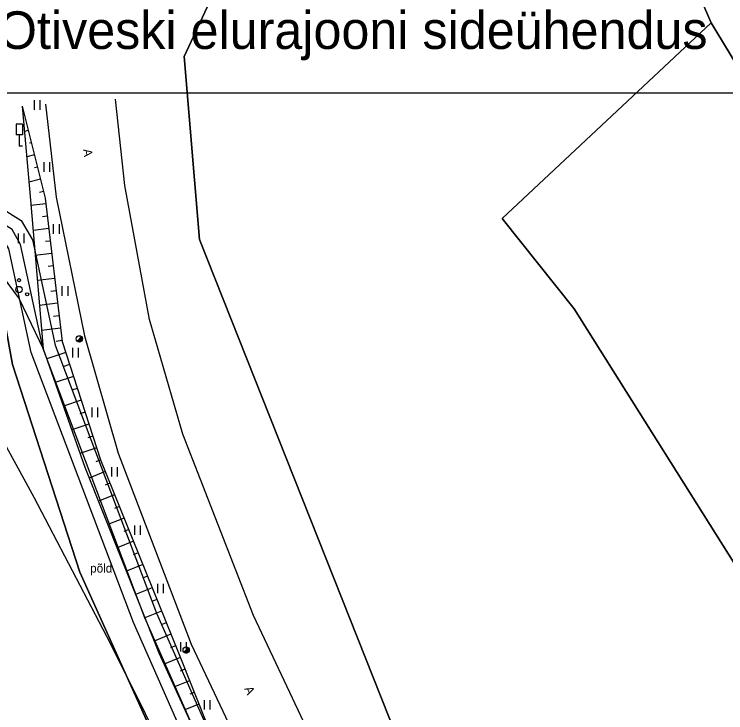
# Model space of a CAD drawing. Extents: x 554947 to 555436, y 6564938 to 6565792.
# Drawn here: x 555060.6 to 555117.3, y 6565555.5 to 6565611.2 of the extents above; entities that cross this region are included whole.
import ezdxf

# ---------------------------------------------------------------- set-up
doc = ezdxf.new("R2010")
doc.units = 0
for name, color, linetype in [('HALJASTUS', 7, 'Continuous'), ('KASUTUSALA', 7, 'Continuous'), ('KPKAABEL', 7, 'Continuous'), ('LIIKLUS', 7, 'Continuous'), ('PIIR', 7, 'Continuous'), ('POST', 7, 'Continuous'), ('PR_SIDE', 7, 'Continuous'), ('PUU', 7, 'Continuous'), ('RELJEEF', 7, 'Continuous'), ('TEE', 7, 'Continuous'), ('VORMISTUS_2', 7, 'Continuous')]:
    doc.layers.add(name, color=color, linetype=linetype)

msp = doc.modelspace()

# ---------------------------------------------------------------- linework, layer by layer
at = {"layer": 'HALJASTUS'}
for p, q in [((555062.138, 6565604.331), (555062.138, 6565603.57)), ((555062.593, 6565604.331), (555062.593, 6565603.57)), ((555062.918, 6565599.392), (555062.918, 6565598.631)), ((555063.373, 6565599.392), (555063.373, 6565598.631)), ((555063.674, 6565594.45), (555063.674, 6565593.689)), ((555064.129, 6565594.45), (555064.129, 6565593.689)), ((555060.874, 6565593.707), (555060.874, 6565592.946)), ((555061.329, 6565593.707), (555061.329, 6565592.946)), ((555064.365, 6565589.498), (555064.365, 6565588.737)), ((555064.82, 6565589.498), (555064.82, 6565588.737)), ((555065.207, 6565584.581), (555065.207, 6565583.82)), ((555065.662, 6565584.581), (555065.662, 6565583.82)), ((555066.741, 6565579.822), (555066.741, 6565579.061)), ((555067.196, 6565579.822), (555067.196, 6565579.061)), ((555068.321, 6565575.079), (555068.321, 6565574.318)), ((555068.776, 6565575.079), (555068.776, 6565574.318)), ((555070.154, 6565570.427), (555070.154, 6565569.666)), ((555070.609, 6565570.427), (555070.609, 6565569.666)), ((555071.986, 6565565.775), (555071.986, 6565565.014)), ((555072.441, 6565565.775), (555072.441, 6565565.014)), ((555073.818, 6565561.123), (555073.818, 6565560.362)), ((555074.273, 6565561.123), (555074.273, 6565560.362)), ((555075.712, 6565556.497), (555075.712, 6565555.735)), ((555076.167, 6565556.497), (555076.167, 6565555.735))]:
    msp.add_line(p, q, dxfattribs=at)
msp.add_lwpolyline([(555033.078, 6565606.955), (555042.182, 6565603.884), (555055.024, 6565596.272), (555056.694, 6565594.201), (555060.942, 6565588.507), (555062.867, 6565584.513)], dxfattribs=at)
at = {"layer": 'KASUTUSALA'}
msp.add_lwpolyline([(555076.534, 6565548.031), (555070.062, 6565562.678), (555061.905, 6565584.227), (555060.115, 6565592.474), (555059.634, 6565593.305), (555058.443, 6565594.054), (555057.954, 6565596.723), (555061.117, 6565594.735), (555062.003, 6565593.204), (555063.828, 6565584.797), (555071.913, 6565563.437), (555078.324, 6565548.927)], dxfattribs=at)
at = {"layer": 'KPKAABEL'}
msp.add_lwpolyline([(555022.085, 6565654.913), (555021.622, 6565652.627), (555021.526, 6565649.765), (555022.786, 6565647.231), (555026.485, 6565641.465), (555030.606, 6565629.728), (555035.378, 6565618.813), (555040.844, 6565608.057), (555047.089, 6565597.805), (555053.567, 6565587.292), (555056.073, 6565583.696), (555062.108, 6565572.667), (555068.248, 6565560.982), (555073.771, 6565549.852), (555080.106, 6565537.978), (555085.958, 6565527.605), (555092.403, 6565515.607), (555098.402, 6565504.536), (555104.641, 6565492.438), (555110.839, 6565480.82), (555116.697, 6565469.072), (555121.821, 6565458.116), (555126.894, 6565446.731), (555132.737, 6565435.388)], dxfattribs=at)
at = {"layer": 'LIIKLUS'}
for p, q in [((555060.71, 6565602.417), (555060.71, 6565601.567)), ((555061.21, 6565602.417), (555060.71, 6565602.417)), ((555061.21, 6565602.417), (555061.21, 6565601.567)), ((555061.21, 6565601.567), (555060.71, 6565601.567)), ((555060.96, 6565601.567), (555060.96, 6565600.667)), ((555061.21, 6565600.667), (555060.96, 6565600.667))]:
    msp.add_line(p, q, dxfattribs=at)
at = {"layer": 'PIIR'}
for points in [[(555016.055, 6565654.913), (555030.24, 6565648.23), (555043.11, 6565640.11), (555053.62, 6565632.14), (555056.61, 6565622.91), (555057.22, 6565600.73), (555060.42, 6565583.26), (555065.78, 6565566.7), (555076.76, 6565542.38), (555113.82, 6565475.68), (554946.63, 6565420.78), (554981.01, 6565316.76), (555160.07, 6565375.54), (555166.64, 6565360.5), (555167.67, 6565357.913)], [(555144.16, 6565410.6), (555124.27, 6565454.45), (555113.82, 6565475.68), (555076.76, 6565542.38), (555065.78, 6565566.7), (555060.42, 6565583.26), (555057.22, 6565600.73), (555056.61, 6565622.91), (555063.43, 6565647.29), (555114.24, 6565634), (555129.77, 6565611.2), (555130.73, 6565621.32), (555138.66, 6565615.26), (555160.12, 6565598.86), (555193.24, 6565604.68), (555193.7, 6565602.7), (555225.47, 6565605.89), (555234.35, 6565605.6), (555251.24, 6565598.48), (555330.71, 6565538.85), (555343.81, 6565536.56), (555350.68, 6565540.44), (555361.56, 6565549.57), (555393.069, 6565582.099)], [(555171.91, 6565394.64), (555091.74, 6565551.94), (555075.34, 6565593.24), (555074.13, 6565607.82), (555079.04, 6565618.4), (555093.56, 6565628.47), (555109.96, 6565624.83), (555116.17, 6565610.5), (555099.5, 6565594.91), (555105.26, 6565587.71), (555119.63, 6565564.84), (555126.35, 6565558.74), (555131.01, 6565550.06), (555139.64, 6565543.1), (555141.68, 6565537.52), (555139.26, 6565529.51), (555139.49, 6565523.98), (555140.65, 6565513.25), (555142.13, 6565499.56), (555141.53, 6565491.02), (555141.65, 6565472.71), (555143.93, 6565463.6), (555153.01, 6565448.47), (555207.22, 6565406.57)], [(555393.069, 6565560.972), (555353.12, 6565523.87), (555343.14, 6565512.46), (555302.6, 6565539.71), (555242.37, 6565583.94), (555179.42, 6565586.32), (555138.98, 6565580.6), (555121.18, 6565602.26), (555116.17, 6565610.5), (555109.96, 6565624.83), (555093.56, 6565628.47), (555079.04, 6565618.4), (555074.13, 6565607.82), (555075.34, 6565593.24), (555091.74, 6565551.94), (555171.91, 6565394.64), (555191.35, 6565341.19), (555195.08, 6565294.61), (555195.28, 6565271.63), (555191.64, 6565237.48)]]:
    msp.add_lwpolyline(points, dxfattribs=at)
msp.add_lwpolyline([(555121.18, 6565602.26), (555138.98, 6565580.6), (555179.42, 6565586.32), (555242.37, 6565583.94), (555302.6, 6565539.71), (555287.77, 6565518.56), (555207.29, 6565506.14), (555200.64, 6565496.23), (555185.97, 6565502.75), (555177.68, 6565506.44), (555171.49, 6565510.85), (555162.05, 6565514.45), (555140.65, 6565513.25), (555139.49, 6565523.98), (555139.26, 6565529.51), (555141.68, 6565537.52), (555139.64, 6565543.1), (555131.01, 6565550.06), (555126.35, 6565558.74), (555119.63, 6565564.84), (555105.26, 6565587.71), (555099.5, 6565594.91), (555116.17, 6565610.5)], close=True, dxfattribs=at)
at = {"layer": 'POST'}
for p, q in [((555065.581, 6565585.125), (555065.934, 6565585.478)), ((555074.1, 6565560.31), (555074.454, 6565560.663))]:
    msp.add_line(p, q, dxfattribs=at)
for centre in [(555065.758, 6565585.302), (555074.278, 6565560.486)]:
    msp.add_circle(centre, 0.25, dxfattribs=at)
for centre, radius, start, end in [((555065.758, 6565585.302), 0.225, 224.8541, 45.0356), ((555065.758, 6565585.302), 0.2, 224.8427, 45.047), ((555065.758, 6565585.302), 0.175, 224.8281, 45.0616), ((555065.758, 6565585.302), 0.15, 224.8087, 45.081), ((555065.758, 6565585.302), 0.125, 224.7814, 45.1083), ((555065.758, 6565585.302), 0.1, 224.7406, 45.1491), ((555065.758, 6565585.302), 0.075, 224.6725, 45.2172), ((555065.758, 6565585.302), 0.05, 224.5363, 45.3534), ((555065.758, 6565585.302), 0.025, 224.1278, 45.7619), ((555074.278, 6565560.486), 0.225, 224.8541, 45.0356), ((555074.278, 6565560.486), 0.2, 224.8427, 45.047), ((555074.278, 6565560.486), 0.175, 224.8281, 45.0616), ((555074.278, 6565560.486), 0.15, 224.8087, 45.081), ((555074.278, 6565560.486), 0.125, 224.7814, 45.1083), ((555074.278, 6565560.486), 0.1, 224.7406, 45.1491), ((555074.278, 6565560.486), 0.075, 224.6725, 45.2172), ((555074.278, 6565560.486), 0.05, 224.5363, 45.3534), ((555074.278, 6565560.486), 0.025, 224.1278, 45.7619)]:
    msp.add_arc(centre, radius, start, end, dxfattribs=at)
at = {"layer": 'PR_SIDE'}
msp.add_lwpolyline([(555136.7, 6565433.435), (555128.282, 6565452.724), (555120.742, 6565469.061), (555112.406, 6565484.723), (555103.739, 6565501.239), (555091.881, 6565522.261), (555081.894, 6565540.539), (555077.43, 6565548.48), (555070.988, 6565563.058), (555062.867, 6565584.513), (555061.059, 6565592.839), (555060.376, 6565594.02), (555051.547, 6565599.57), (555040.593, 6565606.013), (555035.25, 6565616.948), (555028.135, 6565630.971), (555028.178, 6565632.46), (555043.563, 6565658.774)], dxfattribs=at)
at = {"layer": 'PUU'}
for centre, radius in [((555060.934, 6565589.986), 0.125), ((555060.934, 6565589.236), 0.25), ((555061.584, 6565588.861), 0.125)]:
    msp.add_circle(centre, radius, dxfattribs=at)
at = {"layer": 'RELJEEF'}
for p, q in [((555061.435, 6565602.887), (555061.39, 6565602.876)), ((555061.676, 6565601.916), (555061.372, 6565601.841)), ((555061.917, 6565600.946), (555061.78, 6565600.912)), ((555062.158, 6565599.975), (555061.549, 6565599.824)), ((555062.399, 6565599.005), (555062.17, 6565598.948)), ((555062.64, 6565598.034), (555061.725, 6565597.807)), ((555062.88, 6565597.064), (555062.56, 6565596.984)), ((555063.068, 6565596.083), (555061.888, 6565595.943)), ((555063.186, 6565595.09), (555062.823, 6565595.047)), ((555063.304, 6565594.097), (555062.059, 6565593.949)), ((555063.423, 6565593.104), (555063.039, 6565593.059)), ((555063.541, 6565592.111), (555062.229, 6565591.955)), ((555063.659, 6565591.118), (555063.256, 6565591.07)), ((555063.777, 6565590.125), (555062.4, 6565589.962)), ((555063.895, 6565589.132), (555063.472, 6565589.082)), ((555064.013, 6565588.139), (555062.571, 6565587.968)), ((555064.131, 6565587.146), (555063.689, 6565587.094)), ((555064.249, 6565586.153), (555062.742, 6565585.974)), ((555064.367, 6565585.16), (555063.905, 6565585.105)), ((555064.663, 6565584.206), (555063.147, 6565583.714)), ((555064.972, 6565583.255), (555064.524, 6565583.11)), ((555065.281, 6565582.304), (555063.811, 6565581.826)), ((555065.59, 6565581.353), (555065.156, 6565581.212)), ((555065.899, 6565580.402), (555064.474, 6565579.939)), ((555066.209, 6565579.451), (555065.788, 6565579.314)), ((555066.518, 6565578.5), (555065.138, 6565578.052)), ((555066.827, 6565577.549), (555066.42, 6565577.417)), ((555067.136, 6565576.598), (555065.801, 6565576.164)), ((555067.446, 6565575.648), (555067.062, 6565575.492)), ((555067.821, 6565574.72), (555066.534, 6565574.201)), ((555068.195, 6565573.793), (555067.808, 6565573.637)), ((555068.569, 6565572.866), (555067.276, 6565572.344)), ((555068.943, 6565571.938), (555068.555, 6565571.781)), ((555069.318, 6565571.011), (555068.018, 6565570.487)), ((555069.692, 6565570.084), (555069.301, 6565569.926)), ((555070.066, 6565569.156), (555068.761, 6565568.63)), ((555070.44, 6565568.229), (555070.048, 6565568.071)), ((555070.815, 6565567.302), (555069.503, 6565566.772)), ((555071.189, 6565566.374), (555070.794, 6565566.215)), ((555071.563, 6565565.447), (555070.245, 6565564.915)), ((555071.937, 6565564.52), (555071.541, 6565564.36)), ((555072.311, 6565563.592), (555070.988, 6565563.058)), ((555072.686, 6565562.665), (555072.288, 6565562.504)), ((555073.06, 6565561.738), (555071.73, 6565561.201)), ((555073.434, 6565560.81), (555073.034, 6565560.649)), ((555073.807, 6565559.882), (555072.514, 6565559.365)), ((555074.179, 6565558.954), (555073.804, 6565558.804)), ((555074.55, 6565558.026), (555073.343, 6565557.543)), ((555074.922, 6565557.097), (555074.573, 6565556.957)), ((555075.293, 6565556.169), (555074.172, 6565555.72))]:
    msp.add_line(p, q, dxfattribs=at)
for points in [[(555061.195, 6565603.857), (555063.017, 6565596.511), (555064.375, 6565585.09), (555067.439, 6565575.666), (555073.66, 6565560.25), (555078.569, 6565547.982), (555085.069, 6565536.269), (555098.285, 6565513.031), (555109.976, 6565491.648), (555121.815, 6565470.323), (555129.412, 6565453.415), (555139.708, 6565430.653), (555142.38, 6565424.284), (555142.548, 6565422.18)], [(555061.195, 6565603.857), (555061.852, 6565596.368), (555062.867, 6565584.513), (555066.182, 6565575.081), (555072.102, 6565560.271), (555077.804, 6565547.739), (555084.384, 6565535.83), (555097.578, 6565512.389), (555109.285, 6565491.27), (555120.826, 6565469.686), (555128.698, 6565452.867), (555138.479, 6565430.174), (555141.354, 6565423.963), (555142.548, 6565422.18)]]:
    msp.add_lwpolyline(points, dxfattribs=at)
at = {"layer": 'TEE'}
for points in [[(555063.038, 6565604.031), (555063.892, 6565596.591), (555066.154, 6565585.551), (555068.837, 6565576.18), (555074.683, 6565560.943), (555080.389, 6565548.865), (555086.718, 6565537.194), (555099.86, 6565513.945), (555112.002, 6565492.197), (555123.272, 6565470.871), (555131.266, 6565453.894), (555141.635, 6565431.431)], [(555146.697, 6565433.416), (555136.695, 6565455.531), (555128.269, 6565473.276), (555117.193, 6565494.735), (555104.647, 6565516.948), (555091.543, 6565539.738), (555085.215, 6565551.468), (555079.648, 6565563.241), (555074.002, 6565577.71), (555071.343, 6565586.858), (555069.389, 6565597.535), (555068.634, 6565604.431)]]:
    msp.add_lwpolyline(points, dxfattribs=at)
at = {"layer": 'VORMISTUS_2'}
msp.add_lwpolyline([(555186.863, 6565394.913), (555021.863, 6565394.913), (555021.863, 6565604.913), (555186.863, 6565604.913)], close=True, dxfattribs=at)

# ---------------------------------------------------------------- texts
at = {"layer": 'HALJASTUS'}
msp.add_text('põld', height=0.7, rotation=359.9544, dxfattribs=at).set_placement((555066.61, 6565566.661))
at = {"layer": 'TEE'}
for rotation, p in [(277.7014, (555066.045, 6565600.408)), (295.3626, (555078.901, 6565557.402))]:
    msp.add_text('A', height=0.7, rotation=rotation, dxfattribs=at).set_placement(p)
at = {"layer": 'VORMISTUS_2'}
msp.add_text('Kose vald, Tuhala ja Otiveski elurajooni sideühendus', height=3, rotation=360, dxfattribs=at).set_placement((555021.782, 6565608.425))

doc.saveas('drawing.dxf')
